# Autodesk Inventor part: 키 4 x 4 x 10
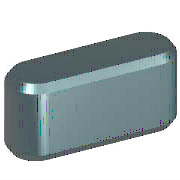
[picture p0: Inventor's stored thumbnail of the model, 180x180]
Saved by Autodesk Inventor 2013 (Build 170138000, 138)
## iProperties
IsCustomPart: 1
Created: 2012-02
Part Number: 키 4 x 4 x 10
Material: 강철, 연강
Description: 키 및 해당 키홈
Document SubType Name: Modeling
Standard: KS B 1311
Designer: test
Standards Organization: KS
Language: ko-KR
Size Designation: 4 x 4 x 10
Categories: <MemberInstance><Categories><Category DisplayName="샤프트 부품" InternalName="7f7aeb1f-a693-4053-b835-cee3144e0d98" Mnemonic="SHFT"><Category DisplayName="키" Interna
Density: 1 g/cm^3
Author: test
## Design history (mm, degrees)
workplane "Work Plane1"
workplane "Work Plane2"
sketch "스케치1"
  geometry: L1 (2, 2)-(8, 2); L2 (8, -2)-(2, -2); L3 (0, 9.4)-(0, -7.4) reference; L4 (-5, 0)-(30, 0) reference; L5 (10, 0)-(10, 7); A1 r 2 centre (2, 0) between (2, 2) and (2, -2); A2 r 2 centre (8, 0) between (8, -2) and (8, 2)
  constraints: 6 end point, 5 point on circle, 4 tangent, 3 point on line, 2 centre point, 1 horizontal, 1 parallel, 1 perpendicular
  dimensions: "d0" = 2 radius of A1 (= 0.5 x PB); "d13" = 2 radius of A2 (= 0.5 x PB); "d14" = 10 distance between parallel lines of L5 L3 (= NLG)
extrude "본체1" new body sketch "스케치1" taper "d3" = 0 deg; stored distance "d4" = 10
workplane "Work Plane3"
body "Solid1"
chamfer "모따기1" distance "d8" = 0.25 (= PHH); stored, may be unused: second distance "d9" = 0.25 (= PHH), angle "d15" = 45 deg
other parameters: "d1" = -2.5 (= -PNT), "d2" = 1.5 (= PH - PNT), "NLG" = 10 [user parameter; used in 3 equation terms], "PB" = 4 [user parameter; used in 2 equation terms], "PNT" = 2.5 [user parameter; used in 2 equation terms], "PH" = 4 [user parameter; used in 1 equation term], "PHH" = 0.25 [user parameter; used in 2 equation terms], "d10" = 0, "d16" = 0, "d17" = 0, "d18" = 0, "WDMAX" = 12 [user parameter], "RR" = 0.08 [user parameter], "PUEB" = 1.8 [user parameter]
